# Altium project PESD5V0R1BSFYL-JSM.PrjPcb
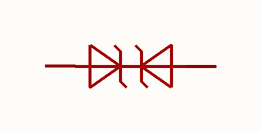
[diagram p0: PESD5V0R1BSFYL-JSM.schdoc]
1 sheet, 1 parts. Net scope: global (net labels, ports and power ports of the same name join across sheets).

## Sheet PESD5V0R1BSFYL-JSM.schdoc
size 127 x 101 mm

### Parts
D?  pesd5v0r1bsfyl-jsm  [DFN0603-2L-BI]  (value not drawn)

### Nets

Not connected (* = marked no-connect by the designer): D? 1(A) 2(K)

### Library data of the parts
D? = pesd5v0r1bsfyl-jsm: 极性:-;反向截止电压(Vrwm):5V;钳位电压:25V;峰值脉冲电流(Ipp):-;峰值脉冲功率(Ppp):100W@8/20us;击穿电压(VBR):6V;; Manufacturer: JSMSEMI(杰盛微); AddInBom: yes; ModelId: 27373427bde74123a6c29df2d43fb649; ModelName: DFN0603-2L-BI-L0.6-W0.3-H0.3; ModelTransform: 23.622,11.811,0,0,0,0,0,0,0; Reverse Stand-Off Voltage (Vrwm): 5V; Clamping Voltage: 25V; Voltage - Breakdown: 6V; Reverse Leakage Current (Ir): 100nA; Number of Channels: 单路; level of protection: IEC 61000-4-4；IEC 61000-4-2; Type: TVS; Junction Capacitance: 0.25pF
